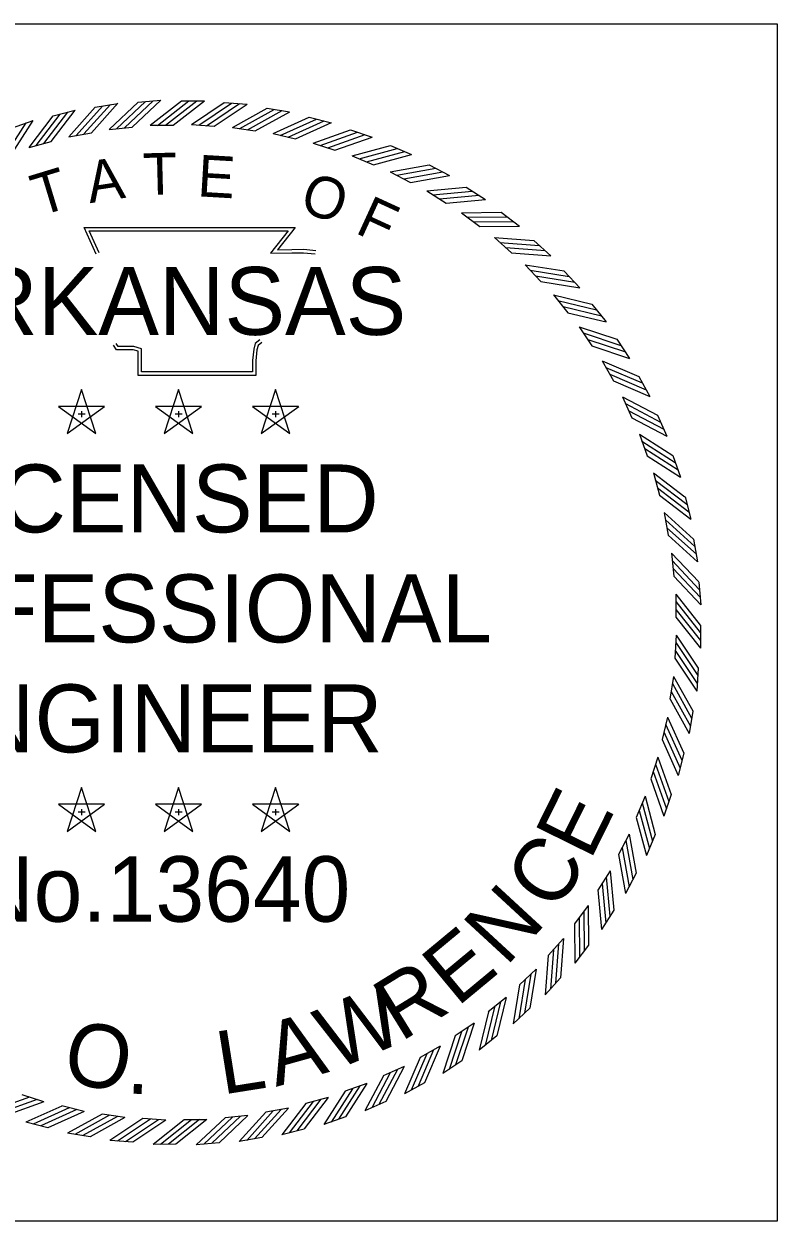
# Model space of a CAD drawing. Extents: x 0 to 1228740, y 0 to 152440.
# Drawn here: x 34.632 to 36.357, y 23.01 to 25.752 of the extents above; entities that cross this region are included whole.
import ezdxf

# ---------------------------------------------------------------- set-up
doc = ezdxf.new("R2010")
doc.units = 0
doc.layers.add('R_No Plot', color=7, linetype='Continuous')
doc.layers.add('STAMP', color=7, linetype='Continuous')

msp = doc.modelspace()

# ---------------------------------------------------------------- linework, layer by layer
at = {"layer": 'R_No Plot'}
msp.add_lwpolyline([(33.6152, 25.7521), (36.3569, 25.7521), (36.3569, 23.0104), (33.6152, 23.0104)], close=True, dxfattribs=at)
at = {"layer": 'STAMP'}
for p, q in [((34.6986, 25.5413), (34.7492, 25.5547)), ((34.7953, 25.5611), (34.8469, 25.5702)), ((34.8934, 25.5728), (34.9456, 25.5776)), ((34.9926, 25.5758), (35.0451, 25.5758)), ((35.0908, 25.5718), (35.1431, 25.568)), ((35.1888, 25.5591), (35.2405, 25.551)), ((34.6037, 25.5136), (34.6531, 25.5311)), ((35.2853, 25.5383), (35.3363, 25.5259)), ((34.7346, 25.4938), (34.7863, 25.5029)), ((34.8273, 25.5107), (34.8796, 25.5156)), ((34.9211, 25.52), (34.9737, 25.52)), ((35.0154, 25.5215), (35.0678, 25.5176)), ((35.1095, 25.5151), (35.1613, 25.507)), ((35.2027, 25.5011), (35.2537, 25.4887)), ((35.3799, 25.5097), (35.4296, 25.4931)), ((34.6436, 25.4692), (34.6944, 25.4826)), ((35.2944, 25.4794), (35.3442, 25.4628)), ((35.4717, 25.4733), (35.5199, 25.4527)), ((35.384, 25.4502), (35.4323, 25.4295)), ((35.5602, 25.4295), (35.6065, 25.4049)), ((35.4709, 25.4136), (35.5174, 25.3891)), ((35.5545, 25.3701), (35.5988, 25.3417)), ((35.6448, 25.3785), (35.689, 25.3502)), ((35.6342, 25.3197), (35.676, 25.2879)), ((35.7249, 25.3207), (35.7666, 25.2889)), ((35.7095, 25.263), (35.7485, 25.2278)), ((35.8, 25.2564), (35.8389, 25.2213)), ((35.7799, 25.2003), (35.8158, 25.1619)), ((35.8695, 25.1862), (35.9053, 25.148)), ((35.8448, 25.1319), (35.8774, 25.0907)), ((35.9329, 25.1105), (35.9655, 25.0695)), ((35.9038, 25.0584), (35.933, 25.0147)), ((35.9899, 25.0298), (36.019, 24.9862)), ((35.9566, 24.9803), (35.9821, 24.9344)), ((36.04, 24.9447), (36.0654, 24.8989)), ((34.7637, 24.9146), (34.7309, 24.814)), ((34.7963, 24.8141), (34.7637, 24.9147)), ((34.9859, 24.9146), (34.9531, 24.814)), ((35.0186, 24.8141), (34.986, 24.9147)), ((35.2082, 24.9146), (35.1754, 24.814)), ((35.2409, 24.8141), (35.2083, 24.9147)), ((36.0028, 24.8981), (36.0243, 24.8502)), ((34.8165, 24.8762), (34.7107, 24.8763)), ((34.7108, 24.8762), (34.7963, 24.8139)), ((34.731, 24.8141), (34.8166, 24.8762)), ((35.0388, 24.8762), (34.933, 24.8763)), ((34.9331, 24.8762), (35.0186, 24.8139)), ((34.9533, 24.8141), (35.0389, 24.8762)), ((35.2611, 24.8762), (35.1553, 24.8763)), ((35.1554, 24.8762), (35.2409, 24.8139)), ((35.1755, 24.8141), (35.2612, 24.8762)), ((34.7561, 24.8593), (34.7719, 24.8593)), ((34.7638, 24.8649), (34.7638, 24.8517)), ((34.9784, 24.8593), (34.9941, 24.8593)), ((34.986, 24.8649), (34.986, 24.8517)), ((35.2007, 24.8593), (35.2164, 24.8593)), ((35.2083, 24.8649), (35.2083, 24.8517)), ((36.083, 24.8558), (36.1045, 24.808)), ((36.042, 24.8124), (36.0595, 24.7629)), ((36.1184, 24.7636), (36.1359, 24.7142)), ((36.074, 24.7237), (36.0874, 24.6729)), ((36.1461, 24.6687), (36.1594, 24.6181)), ((36.0986, 24.6327), (36.1077, 24.581)), ((36.1659, 24.572), (36.175, 24.5204)), ((36.1155, 24.54), (36.1203, 24.4877)), ((36.1776, 24.4739), (36.1824, 24.4217)), ((36.1248, 24.4462), (36.1252, 24.3936)), ((36.1812, 24.3752), (36.1817, 24.3228)), ((36.1262, 24.3519), (36.1224, 24.2995)), ((36.1766, 24.2765), (36.1728, 24.2242)), ((36.1199, 24.2578), (36.1117, 24.206)), ((36.1059, 24.1646), (36.0934, 24.1136)), ((36.1639, 24.1785), (36.1557, 24.1268)), ((36.0841, 24.0729), (36.0675, 24.0231)), ((36.1431, 24.082), (36.1307, 24.031)), ((34.7637, 24.0032), (34.7309, 23.9026)), ((34.7963, 23.9027), (34.7637, 24.0033)), ((34.9859, 24.0032), (34.9531, 23.9026)), ((35.0186, 23.9027), (34.986, 24.0033)), ((35.2082, 24.0032), (35.1754, 23.9026)), ((35.2409, 23.9027), (35.2083, 24.0033)), ((34.8165, 23.9648), (34.7107, 23.9649)), ((34.7108, 23.9648), (34.7963, 23.9025)), ((34.731, 23.9027), (34.8166, 23.9648)), ((35.0388, 23.9648), (34.933, 23.9649)), ((34.9331, 23.9648), (35.0186, 23.9025)), ((34.9533, 23.9027), (35.0389, 23.9648)), ((35.2611, 23.9648), (35.1553, 23.9649)), ((35.1554, 23.9648), (35.2409, 23.9025)), ((35.1755, 23.9027), (35.2612, 23.9648)), ((36.0549, 23.9833), (36.0343, 23.935)), ((36.1144, 23.9874), (36.0979, 23.9377)), ((34.7561, 23.9479), (34.7719, 23.9479)), ((34.7638, 23.9536), (34.7638, 23.9403)), ((34.9784, 23.9479), (34.9941, 23.9479)), ((34.986, 23.9536), (34.986, 23.9403)), ((35.2007, 23.9479), (35.2164, 23.9479)), ((35.2083, 23.9536), (35.2083, 23.9403)), ((36.0184, 23.8964), (35.9938, 23.8499)), ((36.0781, 23.8956), (36.0575, 23.8474)), ((35.9748, 23.8128), (35.9465, 23.7685)), ((36.0342, 23.8071), (36.0097, 23.7608)), ((35.9245, 23.7331), (35.8926, 23.6913)), ((35.9832, 23.7225), (35.955, 23.6783)), ((35.8678, 23.6578), (35.8326, 23.6188)), ((35.9254, 23.6424), (35.8936, 23.6007)), ((35.805, 23.5874), (35.7667, 23.5515)), ((35.8612, 23.5673), (35.8261, 23.5284)), ((35.7367, 23.5225), (35.6955, 23.4899)), ((35.791, 23.4978), (35.7528, 23.462)), ((35.6632, 23.4634), (35.6195, 23.4343)), ((35.7153, 23.4344), (35.6742, 23.4018)), ((35.5851, 23.4107), (35.5391, 23.3852)), ((35.5029, 23.3645), (35.455, 23.343)), ((35.6346, 23.3774), (35.591, 23.3483)), ((35.4172, 23.3253), (35.3676, 23.3078)), ((35.5495, 23.3273), (35.5036, 23.3019)), ((34.6777, 23.2832), (34.6278, 23.2998)), ((35.3285, 23.2933), (35.2777, 23.2799)), ((35.4605, 23.2843), (35.4127, 23.2628)), ((34.7694, 23.2614), (34.7184, 23.2739)), ((34.8626, 23.2474), (34.8107, 23.2555)), ((35.1447, 23.2518), (35.0924, 23.247)), ((35.2375, 23.2687), (35.1857, 23.2596)), ((34.6867, 23.2242), (34.6358, 23.2366)), ((34.9567, 23.2411), (34.9043, 23.2449)), ((35.0509, 23.2425), (34.9984, 23.242)), ((35.3683, 23.2489), (35.3189, 23.2314)), ((34.7833, 23.2034), (34.7315, 23.2116)), ((35.1767, 23.2014), (35.1251, 23.1923)), ((35.2735, 23.2212), (35.2228, 23.2079)), ((34.8813, 23.1907), (34.829, 23.1945)), ((34.9799, 23.1861), (34.9275, 23.1856)), ((35.0787, 23.1897), (35.0265, 23.1849))]:
    msp.add_line(p, q, dxfattribs=at)
for points in [[(34.6943, 25.4826), (34.7493, 25.5547)], [(34.7345, 25.4937), (34.7953, 25.5611)], [(34.7512, 25.4965), (34.8119, 25.5638)], [(34.769, 25.5001), (34.8298, 25.5674)], [(34.7863, 25.5029), (34.847, 25.5703)], [(34.8273, 25.5107), (34.8933, 25.5728)], [(34.8441, 25.5121), (34.9102, 25.5742)], [(34.8622, 25.5142), (34.9282, 25.5762)], [(34.8796, 25.5156), (34.9456, 25.5777)], [(34.9211, 25.5199), (34.9926, 25.5757)], [(34.9379, 25.5198), (35.0094, 25.5756)], [(34.9561, 25.5202), (35.0276, 25.576)], [(34.9736, 25.52), (35.0451, 25.5758)], [(35.0153, 25.5214), (35.0907, 25.5718)], [(35.0321, 25.52), (35.1075, 25.5704)], [(35.0503, 25.5191), (35.1257, 25.5695)], [(35.0677, 25.5177), (35.1431, 25.568)], [(35.1094, 25.5151), (35.1887, 25.5591)], [(35.126, 25.5123), (35.2053, 25.5563)], [(35.1441, 25.5099), (35.2234, 25.5539)], [(34.5878, 25.4491), (34.6367, 25.5255)], [(34.6044, 25.4547), (34.6532, 25.5312)], [(34.6435, 25.4692), (34.6985, 25.5413)], [(34.6599, 25.4733), (34.7148, 25.5454)], [(34.6774, 25.4783), (34.7323, 25.5504)], [(35.1613, 25.507), (35.2406, 25.551)], [(35.2026, 25.501), (35.2853, 25.5383)], [(35.2189, 25.4969), (35.3016, 25.5342)], [(35.2367, 25.493), (35.3194, 25.5303)], [(35.2536, 25.4887), (35.3363, 25.526)], [(35.2943, 25.4793), (35.3798, 25.5097)], [(35.3103, 25.4739), (35.3957, 25.5042)], [(35.3277, 25.4685), (35.4131, 25.4988)], [(35.3442, 25.4628), (35.4296, 25.4931)], [(35.384, 25.4501), (35.4716, 25.4733)], [(35.3994, 25.4434), (35.4871, 25.4665)], [(35.4163, 25.4366), (35.504, 25.4597)], [(35.4323, 25.4296), (35.5199, 25.4527)], [(35.4709, 25.4136), (35.5601, 25.4295)], [(35.4857, 25.4056), (35.575, 25.4214)], [(35.502, 25.3974), (35.5912, 25.4133)], [(35.5173, 25.3891), (35.6066, 25.405)], [(35.5545, 25.3701), (35.6447, 25.3785)], [(35.5686, 25.3608), (35.6589, 25.3692)], [(35.5841, 25.3514), (35.6744, 25.3598)], [(35.5987, 25.3418), (35.689, 25.3502)], [(35.6342, 25.3197), (35.7248, 25.3207)], [(35.6475, 25.3094), (35.7381, 25.3103)], [(34.7974, 25.225), (34.7695, 25.2855), (35.2528, 25.2858), (35.2124, 25.2351), (35.2452, 25.2355), (35.2727, 25.2359), (35.3001, 25.2329)], [(35.6622, 25.2987), (35.7529, 25.2996)], [(35.676, 25.2879), (35.7666, 25.2889)], [(34.8044, 25.2282), (34.7814, 25.2779), (35.2369, 25.2781), (35.1964, 25.2272), (35.2453, 25.2278), (35.2723, 25.2282), (35.2992, 25.2253)], [(35.7095, 25.263), (35.7999, 25.2564)], [(35.7219, 25.2516), (35.8123, 25.245)], [(35.7356, 25.2397), (35.8261, 25.2331)], [(35.7485, 25.2279), (35.8389, 25.2213)], [(35.7798, 25.2003), (35.8694, 25.1863)], [(35.7912, 25.1879), (35.8808, 25.1738)], [(35.804, 25.1749), (35.8935, 25.1608)], [(35.8158, 25.162), (35.9054, 25.148)], [(35.8447, 25.1319), (35.9328, 25.1106)], [(35.8551, 25.1186), (35.9432, 25.0972)], [(35.8667, 25.1046), (35.9548, 25.0832)], [(35.8774, 25.0908), (35.9655, 25.0695)], [(35.9038, 25.0584), (35.9898, 25.0299)], [(35.913, 25.0443), (35.9991, 25.0158)], [(35.1766, 25.0225), (35.1684, 25.0158), (35.1656, 25.0058), (35.1629, 24.9807), (35.1629, 24.9473), (34.8931, 24.9473), (34.8931, 24.9924), (34.8931, 25.0024), (34.8822, 25.0058), (34.8438, 25.0058), (34.837, 25.0162)], [(35.1718, 25.0284), (35.1616, 25.0202), (35.1581, 25.0072), (35.1552, 24.9811), (35.1552, 24.955), (34.9008, 24.955), (34.9008, 24.9924), (34.9008, 25.0081), (34.8833, 25.0134), (34.8479, 25.0134), (34.8434, 25.0204)], [(35.9234, 25.0294), (36.0095, 25.0008)], [(35.933, 25.0148), (36.019, 24.9862)], [(35.9566, 24.9803), (36.04, 24.9448)], [(35.9646, 24.9655), (36.048, 24.9299)], [(35.9737, 24.9498), (36.0572, 24.9142)], [(35.9821, 24.9344), (36.0655, 24.8988)], [(36.0027, 24.8982), (36.0829, 24.8558)], [(36.0095, 24.8827), (36.0897, 24.8404)], [(36.0173, 24.8663), (36.0975, 24.8239)], [(36.0243, 24.8503), (36.1045, 24.8079)], [(36.0419, 24.8124), (36.1183, 24.7636)], [(36.0474, 24.7965), (36.1238, 24.7477)], [(36.0539, 24.7795), (36.1303, 24.7306)], [(36.0595, 24.7629), (36.1359, 24.7141)], [(36.0739, 24.7238), (36.146, 24.6688)], [(36.0781, 24.7074), (36.1502, 24.6525)], [(36.0831, 24.6899), (36.1552, 24.635)], [(36.0874, 24.673), (36.1595, 24.618)], [(36.0985, 24.6328), (36.1658, 24.572)], [(36.1013, 24.6161), (36.1686, 24.5554)], [(36.1048, 24.5983), (36.1722, 24.5375)], [(36.1077, 24.581), (36.175, 24.5203)], [(36.1155, 24.54), (36.1776, 24.474)], [(36.1169, 24.5232), (36.1789, 24.4571)], [(36.1189, 24.5051), (36.181, 24.4391)], [(36.1204, 24.4877), (36.1825, 24.4217)], [(36.1247, 24.4462), (36.1811, 24.3752)], [(36.1247, 24.4294), (36.1811, 24.3584)], [(36.1253, 24.4112), (36.1817, 24.3402)], [(36.1253, 24.3937), (36.1817, 24.3227)], [(36.1262, 24.352), (36.1766, 24.2766)], [(36.1248, 24.3352), (36.1752, 24.2598)], [(36.1224, 24.2996), (36.1728, 24.2242)], [(36.1239, 24.317), (36.1742, 24.2416)], [(36.1171, 24.2413), (36.1611, 24.162)], [(36.1199, 24.2579), (36.1638, 24.1786)], [(36.1147, 24.2232), (36.1586, 24.1439)], [(36.1118, 24.206), (36.1558, 24.1267)], [(36.1058, 24.1647), (36.1431, 24.082)], [(36.0978, 24.1306), (36.135, 24.0479)], [(36.1017, 24.1484), (36.1389, 24.0657)], [(36.0935, 24.1136), (36.1307, 24.031)], [(36.0841, 24.073), (36.1144, 23.9875)], [(36.0786, 24.057), (36.1089, 23.9716)], [(36.0676, 24.0231), (36.0979, 23.9377)], [(36.0733, 24.0396), (36.1036, 23.9542)], [(36.0481, 23.9679), (36.0713, 23.8802)], [(36.0549, 23.9833), (36.0781, 23.8957)], [(36.0413, 23.951), (36.0645, 23.8633)], [(36.0343, 23.935), (36.0575, 23.8474)], [(36.0104, 23.8816), (36.0262, 23.7923)], [(36.0184, 23.8964), (36.0342, 23.8072)], [(36.0022, 23.8653), (36.018, 23.7761)], [(35.9939, 23.85), (36.0097, 23.7607)], [(35.9656, 23.7987), (35.974, 23.7084)], [(35.9748, 23.8128), (35.9832, 23.7226)], [(35.9561, 23.7832), (35.9645, 23.6929)], [(35.9466, 23.7686), (35.955, 23.6783)], [(35.9142, 23.7198), (35.9151, 23.6292)], [(35.9245, 23.7331), (35.9254, 23.6425)], [(35.8927, 23.6913), (35.8936, 23.6007)], [(35.9034, 23.7051), (35.9043, 23.6144)], [(35.8564, 23.6454), (35.8498, 23.555)], [(35.8678, 23.6578), (35.8612, 23.5674)], [(35.8326, 23.6188), (35.8261, 23.5284)], [(35.8445, 23.6317), (35.8379, 23.5412)], [(35.805, 23.5875), (35.791, 23.4979)], [(35.7668, 23.5515), (35.7528, 23.4619)], [(35.7796, 23.5633), (35.7656, 23.4738)], [(35.7926, 23.5761), (35.7786, 23.4865)], [(35.7094, 23.5006), (35.688, 23.4125)], [(35.7234, 23.5122), (35.702, 23.4241)], [(35.7367, 23.5226), (35.7153, 23.4345)], [(35.6956, 23.4899), (35.6742, 23.4018)], [(35.6342, 23.4439), (35.6056, 23.3578)], [(35.6491, 23.4543), (35.6205, 23.3682)], [(35.6632, 23.4635), (35.6346, 23.3775)], [(35.6196, 23.4343), (35.591, 23.3483)], [(35.5545, 23.3935), (35.519, 23.3101)], [(35.5703, 23.4027), (35.5347, 23.3193)], [(35.5851, 23.4107), (35.5495, 23.3273)], [(35.5029, 23.3646), (35.4606, 23.2844)], [(35.5392, 23.3852), (35.5036, 23.3018)], [(35.4551, 23.343), (35.4127, 23.2628)], [(35.471, 23.35), (35.4287, 23.2698)], [(35.4875, 23.3578), (35.4451, 23.2776)], [(35.3677, 23.3078), (35.3189, 23.2314)], [(35.3842, 23.3134), (35.3354, 23.237)], [(35.4012, 23.3199), (35.3524, 23.2435)], [(35.4172, 23.3254), (35.3684, 23.249)], [(34.6444, 23.294), (34.5589, 23.2637)], [(34.6618, 23.2887), (34.5763, 23.2583)], [(34.6777, 23.2832), (34.5923, 23.2529)], [(35.2778, 23.2799), (35.2228, 23.2078)], [(35.2947, 23.2842), (35.2397, 23.2121)], [(35.3122, 23.2892), (35.2572, 23.2171)], [(35.3285, 23.2934), (35.2736, 23.2213)], [(34.7184, 23.2738), (34.6358, 23.2366)], [(34.7353, 23.2695), (34.6527, 23.2323)], [(34.7531, 23.2656), (34.6705, 23.2284)], [(34.7695, 23.2615), (34.6868, 23.2242)], [(34.8108, 23.2555), (34.7315, 23.2115)], [(34.828, 23.2526), (34.7487, 23.2087)], [(34.846, 23.2502), (34.7667, 23.2062)], [(35.128, 23.2504), (35.0619, 23.1884)], [(35.1448, 23.2518), (35.0787, 23.1897)], [(35.1858, 23.2596), (35.1251, 23.1923)], [(35.203, 23.2625), (35.1423, 23.1951)], [(35.2209, 23.266), (35.1602, 23.1987)], [(35.2375, 23.2688), (35.1768, 23.2015)], [(34.8627, 23.2474), (34.7834, 23.2035)], [(34.9043, 23.2449), (34.8289, 23.1945)], [(34.9217, 23.2434), (34.8463, 23.1931)], [(34.9399, 23.2425), (34.8645, 23.1921)], [(34.9567, 23.2411), (34.8813, 23.1907)], [(34.9985, 23.242), (34.9275, 23.1856)], [(35.0159, 23.242), (34.9449, 23.1856)], [(35.0341, 23.2426), (34.9631, 23.1862)], [(35.051, 23.2426), (34.98, 23.1862)], [(35.0925, 23.2469), (35.0264, 23.1848)], [(35.1099, 23.2484), (35.0438, 23.1863)]]:
    msp.add_lwpolyline(points, dxfattribs=at)

# ---------------------------------------------------------------- texts
for s, height, rotation, p in [('A', 0.0953, 8.6788, (34.7827, 25.3414)), ('T', 0.0953, 1.4789, (34.9058, 25.3603)), ('E', 0.0953, 356.672, (35.0278, 25.3575)), ('T', 0.0953, 16.9015, (34.6669, 25.3112)), ('O', 0.0953, 341.2218, (35.2593, 25.3248)), ('F', 0.0953, 335.3628, (35.3878, 25.2745)), ('E', 0.1448, 63.7362, (35.9287, 23.8339)), ('C', 0.1448, 56.0754, (35.8474, 23.7138)), ('N', 0.1448, 47.3202, (35.7358, 23.5913)), ('E', 0.1448, 39.6594, (35.6239, 23.499)), ('R', 0.1448, 31.6338, (35.4945, 23.4193)), ('W', 0.1448, 22.8786, (35.3423, 23.3539)), ('A', 0.1448, 15.5826, (35.209, 23.3176)), ('O', 0.1448, 349.3169, (34.7158, 23.331)), ('L', 0.1448, 9.0162, (35.0859, 23.2997)), ('.', 0.1448, 357.3425, (34.8651, 23.3029))]:
    msp.add_text(s, height=height, rotation=rotation, dxfattribs=at).set_placement(p)
for s, height, p in [('ARKANSAS', 0.15559, (34.3744, 25.0399)), ('LICENSED', 0.15559, (34.404, 24.5876)), ('PROFESSIONAL', 0.155594, (34.0854, 24.3357)), ('ENGINEER', 0.15559, (34.367, 24.0838)), ('No.13640', 0.15004, (34.5092, 23.6959))]:
    msp.add_text(s, height=height, dxfattribs=at).set_placement(p)

doc.saveas('drawing.dxf')
